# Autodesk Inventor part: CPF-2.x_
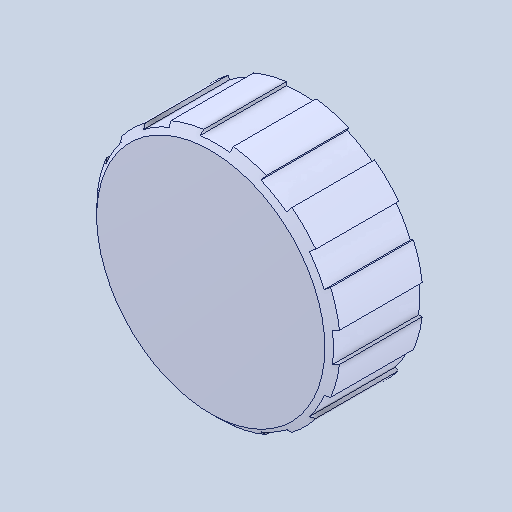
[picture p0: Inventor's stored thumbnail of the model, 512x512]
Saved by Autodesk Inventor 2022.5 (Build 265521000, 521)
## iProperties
Created: 2024-09
Part Number: CPF-2.x_
Material: 一般
Document SubType Name: Modeling
Designer: ImaoCorp
Density: 1 g/cm^3
Appearance: 既定
Author: ImaoCorp
Sending System: SOLIDWORKS 2022-2022290
MC: AMD64
MC_MODEL: Intel64 Family 6 Model 60 Stepping 3, GenuineIntel
OS: Windows_NT
FRU: Parasolid Version 33.1, build 260,  4-25-2022
FORMAT: text
GUISE: transmit
KEY: FILECPF-2.x_t
DATE: Tue Sep  3 09:29:15 2024
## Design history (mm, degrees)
feature "Base1"
node "ソリッド1"
